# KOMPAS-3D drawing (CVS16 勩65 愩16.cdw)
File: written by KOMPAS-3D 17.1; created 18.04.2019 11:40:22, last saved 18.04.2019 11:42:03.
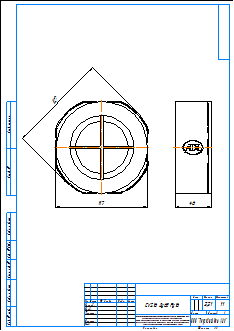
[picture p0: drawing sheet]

Sheet 1: A3, portrait

Title block, sheet 1: name: CVS16 Ду65 Ру16; material: Внимание! Данный продукт является объектом авторского права ООО «Торговый Дом АДЛ». / Запрещается изменение, копирование, распространение / (в том числе путем копирования на другие сайты и ресурсы в Интернете) / или любое иное использование информации и объектов без предварительного / согласия правообладателя (ООО «Торговый Дом АДЛ»).; mass: 2,21; sheets: 1; organisation: ООО "Торговый дом АДЛ"; sheet format: A3

Views: Вид 1, Проекционный вид 2
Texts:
  user
Dimensions and other numbers on the sheet: 127; 117; 46; 1:1; 1; 2,21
